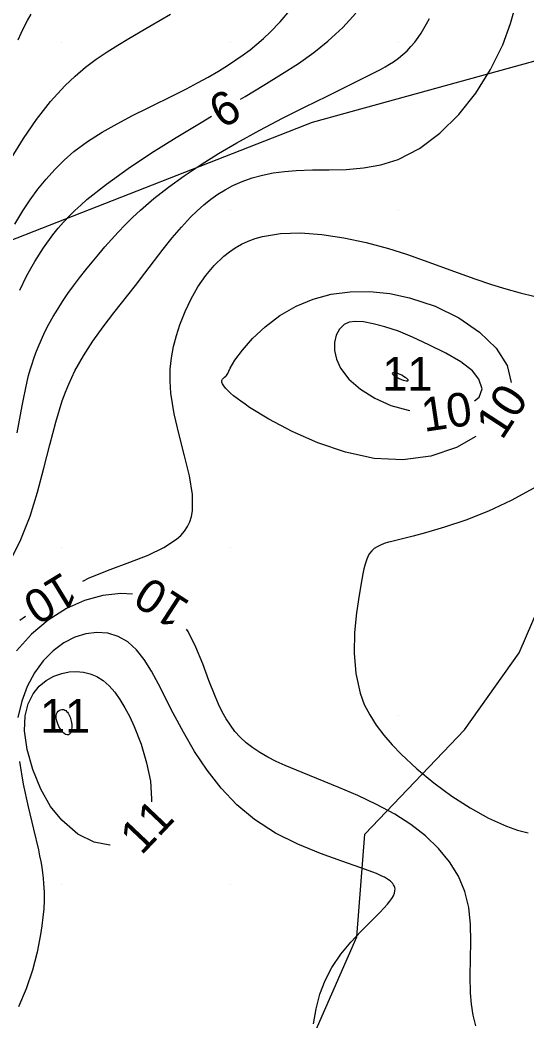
# Model space of a CAD drawing. Extents: x 2602990 to 2605851, y 618069 to 619180.
# Drawn here: x 2603217.5 to 2603247.6, y 618261.9 to 618321.3 of the extents above; entities that cross this region are included whole.
import ezdxf

# ---------------------------------------------------------------- set-up
doc = ezdxf.new("R2010")
doc.units = 0
for name, color, linetype in [('DTM Contours Major', 7, 'Continuous'), ('DTM Contours Major Text', 7, 'Continuous'), ('DTM Contours Minor', 7, 'Continuous'), ('DTM Contours Minor Text', 7, 'Continuous'), ('Exist DTM QL2 LIDAR Elevation Point', 7, 'Continuous'), ('PH Exist DTM Obscure Area', 7, 'Continuous')]:
    doc.layers.add(name, color=color, linetype=linetype)

msp = doc.modelspace()

# ---------------------------------------------------------------- linework, layer by layer
at = {"layer": 'DTM Contours Major'}
for points in [[(2603221.249, 618288.003), (2603221.638, 618288.187), (2603222.872, 618288.685), (2603224.049, 618289.127), (2603225.129, 618289.548), (2603226.068, 618289.987), (2603226.825, 618290.481), (2603227.081, 618290.715), (2603227.298, 618290.966), (2603227.475, 618291.237), (2603227.613, 618291.527), (2603227.713, 618291.839), (2603227.776, 618292.174), (2603227.775, 618293.15), (2603227.593, 618294.252), (2603227.3, 618295.44), (2603226.969, 618296.679), (2603226.67, 618297.929), (2603226.474, 618299.154), (2603226.432, 618299.878), (2603226.451, 618300.581), (2603226.524, 618301.265), (2603226.648, 618301.933), (2603226.816, 618302.587), (2603227.023, 618303.229), (2603227.327, 618304.008), (2603227.684, 618304.761), (2603228.091, 618305.477), (2603228.55, 618306.146), (2603229.06, 618306.755), (2603229.62, 618307.293), (2603229.955, 618307.558), (2603230.307, 618307.796), (2603230.677, 618308.008), (2603231.068, 618308.192), (2603231.481, 618308.347), (2603231.917, 618308.472), (2603232.999, 618308.648), (2603234.185, 618308.683), (2603235.446, 618308.595), (2603236.755, 618308.399), (2603238.087, 618308.113), (2603239.412, 618307.752), (2603240.476, 618307.415), (2603241.519, 618307.054), (2603243.548, 618306.309), (2603244.538, 618305.953), (2603245.512, 618305.626), (2603246.374, 618305.365), (2603247.219, 618305.132), (2603248.043, 618304.919)], [(2603248.03, 618293.517), (2603246.696, 618292.78), (2603245.334, 618292.152), (2603243.996, 618291.628), (2603242.737, 618291.201), (2603241.61, 618290.867), (2603240.878, 618290.672), (2603239.533, 618290.337), (2603239.409, 618290.303), (2603239.155, 618290.224), (2603238.929, 618290.138), (2603238.73, 618290.04), (2603238.556, 618289.926), (2603238.406, 618289.792), (2603238.279, 618289.633), (2603238.177, 618289.454), (2603238.092, 618289.246), (2603238.017, 618289.007), (2603237.95, 618288.735), (2603237.885, 618288.428), (2603237.818, 618288.085), (2603237.654, 618287.17), (2603237.496, 618286.104), (2603237.386, 618284.939), (2603237.36, 618283.723), (2603237.458, 618282.507), (2603237.718, 618281.342), (2603237.97, 618280.677), (2603238.291, 618280.044), (2603238.676, 618279.436), (2603239.12, 618278.848), (2603239.619, 618278.274), (2603240.166, 618277.708), (2603241.096, 618276.843), (2603242.106, 618276.009), (2603243.169, 618275.227), (2603244.259, 618274.523), (2603245.35, 618273.92), (2603246.416, 618273.441), (2603247.067, 618273.212), (2603247.695, 618273.048)], [(2603217.523, 618285.68), (2603217.847, 618285.921)]]:
    msp.add_lwpolyline(points, dxfattribs=at)
at = {"layer": 'DTM Contours Minor'}
for points in [[(2603216.947, 618289.189), (2603217.581, 618290.475), (2603218.122, 618291.862), (2603218.566, 618293.281), (2603218.947, 618294.703), (2603219.297, 618296.102), (2603219.65, 618297.448), (2603220.038, 618298.714), (2603220.221, 618299.218), (2603220.418, 618299.705), (2603220.595, 618300.1), (2603220.785, 618300.487), (2603221.291, 618301.389), (2603221.856, 618302.258), (2603222.464, 618303.102), (2603223.098, 618303.928), (2603224.383, 618305.553), (2603224.943, 618306.282), (2603226.031, 618307.709), (2603226.568, 618308.386), (2603227.108, 618309.026), (2603227.655, 618309.619), (2603228.047, 618310.002), (2603228.447, 618310.357), (2603228.857, 618310.683), (2603229.279, 618310.981), (2603229.714, 618311.25), (2603230.165, 618311.49), (2603230.726, 618311.739), (2603231.313, 618311.947), (2603231.926, 618312.116), (2603232.566, 618312.247), (2603233.234, 618312.34), (2603233.931, 618312.397), (2603234.884, 618312.425), (2603235.876, 618312.433), (2603236.893, 618312.459), (2603237.924, 618312.544), (2603238.956, 618312.727), (2603239.976, 618313.047), (2603241.248, 618313.7), (2603242.457, 618314.602), (2603243.579, 618315.711), (2603244.591, 618316.985), (2603245.467, 618318.382), (2603246.185, 618319.861), (2603246.647, 618321.116), (2603247.007, 618322.38)], [(2603216.996, 618313.095), (2603217.729, 618314.291), (2603218.506, 618315.429), (2603219.326, 618316.483), (2603220.187, 618317.43), (2603220.795, 618318.003), (2603221.418, 618318.523), (2603222.051, 618318.998), (2603222.692, 618319.435), (2603223.337, 618319.844), (2603223.981, 618320.232), (2603225.24, 618320.961), (2603226.468, 618321.671)], [(2603217.213, 618309.205), (2603217.695, 618309.993), (2603218.131, 618310.649), (2603218.589, 618311.28), (2603219.074, 618311.884), (2603219.59, 618312.458), (2603220.14, 618313.002), (2603220.731, 618313.513), (2603221.536, 618314.111), (2603222.395, 618314.661), (2603223.291, 618315.173), (2603224.209, 618315.655), (2603225.131, 618316.114), (2603226.73, 618316.903), (2603227.402, 618317.245), (2603228.057, 618317.591), (2603228.693, 618317.942), (2603229.312, 618318.301), (2603229.912, 618318.673), (2603230.347, 618318.959), (2603230.772, 618319.256), (2603231.188, 618319.566), (2603231.594, 618319.891), (2603231.992, 618320.235), (2603232.383, 618320.6), (2603232.979, 618321.218), (2603233.55, 618321.888)], [(2603217.414, 618320.163), (2603217.591, 618320.554), (2603217.777, 618320.934), (2603217.975, 618321.306), (2603218.186, 618321.671)], [(2603230.62, 618316.632), (2603230.898, 618316.796), (2603232.005, 618317.455), (2603233.061, 618318.106), (2603234.054, 618318.755), (2603234.974, 618319.41), (2603235.812, 618320.078), (2603236.265, 618320.481), (2603236.688, 618320.893), (2603237.084, 618321.313), (2603237.457, 618321.742)], [(2603217.348, 618296.799), (2603217.648, 618298.418), (2603217.744, 618298.914), (2603217.842, 618299.39), (2603217.947, 618299.849), (2603218.037, 618300.207), (2603218.134, 618300.556), (2603218.238, 618300.897), (2603218.349, 618301.232), (2603218.468, 618301.563), (2603218.597, 618301.89), (2603218.794, 618302.35), (2603219.009, 618302.806), (2603219.243, 618303.26), (2603219.495, 618303.711), (2603219.764, 618304.16), (2603220.05, 618304.608), (2603220.369, 618305.076), (2603220.704, 618305.543), (2603221.057, 618306.011), (2603221.425, 618306.481), (2603221.807, 618306.953), (2603222.204, 618307.429), (2603222.569, 618307.858), (2603222.949, 618308.29), (2603223.346, 618308.725), (2603223.766, 618309.162), (2603224.211, 618309.601), (2603224.687, 618310.042), (2603225.481, 618310.72), (2603226.349, 618311.397), (2603227.282, 618312.071), (2603228.275, 618312.738), (2603229.32, 618313.394), (2603230.409, 618314.038), (2603231.756, 618314.785), (2603233.121, 618315.501), (2603234.466, 618316.181), (2603235.757, 618316.816), (2603238.025, 618317.926), (2603238.652, 618318.244), (2603238.939, 618318.397), (2603239.21, 618318.549), (2603239.466, 618318.701), (2603239.706, 618318.856), (2603239.993, 618319.061), (2603240.26, 618319.277), (2603240.508, 618319.505), (2603240.74, 618319.75), (2603240.961, 618320.012), (2603241.171, 618320.297), (2603241.34, 618320.549), (2603241.505, 618320.819), (2603241.669, 618321.107), (2603241.832, 618321.413)], [(2603217.507, 618305.282), (2603217.932, 618306.145), (2603218.399, 618306.986), (2603218.913, 618307.798), (2603219.477, 618308.575), (2603219.787, 618308.956), (2603220.113, 618309.329), (2603220.458, 618309.695), (2603220.786, 618310.019), (2603221.133, 618310.341), (2603221.502, 618310.665), (2603222.651, 618311.582), (2603223.941, 618312.508), (2603225.334, 618313.434), (2603226.791, 618314.351), (2603228.276, 618315.25), (2603228.898, 618315.616)], [(2603229.779, 618300.221), (2603229.825, 618300.269), (2603229.86, 618300.324), (2603229.922, 618300.463), (2603230, 618300.647), (2603230.278, 618301.122), (2603230.728, 618301.727), (2603231.334, 618302.407), (2603232.079, 618303.106), (2603232.946, 618303.768), (2603233.918, 618304.338), (2603234.932, 618304.754), (2603236.01, 618305.035), (2603237.138, 618305.183), (2603238.299, 618305.198), (2603239.477, 618305.081), (2603240.658, 618304.834), (2603242.168, 618304.323), (2603243.579, 618303.629), (2603244.813, 618302.788), (2603245.794, 618301.836), (2603246.446, 618300.811), (2603246.68, 618299.802)], [(2603240, 618302.845), (2603239.178, 618303.096), (2603238.49, 618303.28), (2603237.921, 618303.392), (2603237.455, 618303.426), (2603237.075, 618303.375), (2603236.766, 618303.234), (2603236.493, 618302.97), (2603236.299, 618302.61), (2603236.196, 618302.177), (2603236.195, 618301.691), (2603236.309, 618301.175), (2603236.55, 618300.651), (2603237.054, 618299.997), (2603237.749, 618299.392), (2603238.594, 618298.864), (2603239.551, 618298.439), (2603240.578, 618298.144), (2603240.668, 618298.132)], [(2603244.516, 618298.703), (2603244.789, 618298.926), (2603244.974, 618299.428), (2603244.764, 618300), (2603244.398, 618300.499), (2603243.705, 618301.022), (2603242.802, 618301.543), (2603241.806, 618302.037), (2603240.833, 618302.48), (2603240, 618302.845)], [(2603240, 618300.314), (2603239.911, 618300.344), (2603239.833, 618300.364), (2603239.766, 618300.374), (2603239.711, 618300.375), (2603239.67, 618300.369), (2603239.643, 618300.357), (2603239.632, 618300.336), (2603239.637, 618300.31), (2603239.659, 618300.28), (2603239.694, 618300.245), (2603239.798, 618300.168), (2603239.884, 618300.117), (2603240.081, 618300.018), (2603240.281, 618299.939), (2603240.373, 618299.911), (2603240.448, 618299.894), (2603240.51, 618299.887), (2603240.552, 618299.894), (2603240.571, 618299.914), (2603240.564, 618299.949), (2603240.526, 618300), (2603240.473, 618300.046), (2603240.395, 618300.102), (2603240.301, 618300.163), (2603240.199, 618300.223), (2603240.096, 618300.275), (2603240, 618300.314)], [(2603244.587, 618296.588), (2603243.45, 618295.942), (2603241.921, 618295.424), (2603240.258, 618295.196), (2603238.558, 618295.29), (2603236.857, 618295.651), (2603235.211, 618296.206), (2603233.676, 618296.883), (2603232.307, 618297.612), (2603231.16, 618298.32), (2603230.889, 618298.503), (2603230.64, 618298.679), (2603230.413, 618298.847), (2603230.211, 618299.007), (2603230.032, 618299.159), (2603229.878, 618299.302), (2603229.736, 618299.453), (2603229.627, 618299.591), (2603229.554, 618299.716), (2603229.516, 618299.826), (2603229.517, 618299.921), (2603229.556, 618300), (2603229.584, 618300.04), (2603229.662, 618300.112), (2603229.745, 618300.182), (2603229.779, 618300.221)], [(2603224.201, 618287.219), (2603223.508, 618287.265), (2603222.437, 618287.146), (2603221.351, 618286.845), (2603220.283, 618286.371), (2603219.201, 618285.685), (2603218.206, 618284.837), (2603217.324, 618283.857)], [(2603234.955, 618261.697), (2603235.101, 618262.592), (2603235.33, 618263.453), (2603235.643, 618264.272), (2603236.04, 618265.043), (2603236.569, 618265.828), (2603237.162, 618266.549), (2603237.778, 618267.206), (2603238.913, 618268.334), (2603239.35, 618268.806), (2603239.49, 618268.981), (2603239.605, 618269.146), (2603239.694, 618269.302), (2603239.756, 618269.45), (2603239.789, 618269.591), (2603239.792, 618269.724), (2603239.778, 618269.806), (2603239.75, 618269.886), (2603239.709, 618269.963), (2603239.655, 618270.039), (2603239.587, 618270.112), (2603239.506, 618270.184), (2603239.405, 618270.259), (2603239.29, 618270.333), (2603239.16, 618270.406), (2603239.016, 618270.479), (2603238.857, 618270.553), (2603238.684, 618270.626), (2603237.758, 618270.971), (2603236.628, 618271.359), (2603235.363, 618271.815), (2603234.031, 618272.363), (2603232.702, 618273.028), (2603231.446, 618273.835), (2603230.405, 618274.712), (2603229.473, 618275.698), (2603228.639, 618276.765), (2603227.893, 618277.881), (2603227.226, 618279.017), (2603226.626, 618280.143), (2603225.757, 618281.868), (2603225.337, 618282.642), (2603224.903, 618283.332), (2603224.44, 618283.919), (2603223.929, 618284.383), (2603223.359, 618284.709), (2603222.742, 618284.896), (2603222.094, 618284.949), (2603221.431, 618284.871), (2603220.771, 618284.667), (2603220.129, 618284.339), (2603219.485, 618283.861), (2603218.897, 618283.26), (2603218.382, 618282.55), (2603217.957, 618281.745), (2603217.638, 618280.857), (2603217.395, 618279.904)], [(2603244.587, 618261.584), (2603244.441, 618262.212), (2603244.339, 618262.866), (2603244.279, 618263.543), (2603244.258, 618264.535), (2603244.298, 618266.582), (2603244.277, 618267.605), (2603244.173, 618268.605), (2603243.946, 618269.566), (2603243.565, 618270.475), (2603243.035, 618271.327), (2603242.375, 618272.121), (2603241.601, 618272.857), (2603240.728, 618273.532), (2603239.775, 618274.147), (2603238.701, 618274.731), (2603237.585, 618275.258), (2603236.455, 618275.74), (2603234.269, 618276.621), (2603233.271, 618277.043), (2603232.738, 618277.29), (2603232.239, 618277.544), (2603231.775, 618277.809), (2603231.345, 618278.093), (2603230.95, 618278.399), (2603230.59, 618278.733), (2603230.29, 618279.068), (2603230.016, 618279.431), (2603229.765, 618279.822), (2603229.532, 618280.239), (2603229.315, 618280.684), (2603229.11, 618281.154), (2603228.742, 618282.102), (2603228.373, 618283.091), (2603227.973, 618284.073), (2603227.511, 618284.998), (2603227.416, 618285.138)], [(2603217.823, 618280), (2603218.012, 618280.716), (2603218.298, 618281.295), (2603218.66, 618281.749), (2603219.078, 618282.094), (2603219.531, 618282.342), (2603220, 618282.509), (2603220.438, 618282.601), (2603220.868, 618282.63), (2603221.288, 618282.596), (2603221.696, 618282.496), (2603222.088, 618282.327), (2603222.461, 618282.089), (2603222.814, 618281.78), (2603223.147, 618281.405), (2603223.461, 618280.969), (2603223.758, 618280.478), (2603224.039, 618279.937), (2603224.306, 618279.351), (2603224.71, 618278.305), (2603225.042, 618277.206), (2603225.264, 618276.105), (2603225.342, 618275.054), (2603225.324, 618274.888)], [(2603219.68, 618280), (2603219.701, 618280.108), (2603219.741, 618280.196), (2603219.795, 618280.266), (2603219.859, 618280.317), (2603219.929, 618280.351), (2603220, 618280.369), (2603220.064, 618280.371), (2603220.126, 618280.361), (2603220.185, 618280.338), (2603220.24, 618280.304), (2603220.292, 618280.26), (2603220.341, 618280.207), (2603220.386, 618280.146), (2603220.427, 618280.077), (2603220.464, 618280.002), (2603220.497, 618279.922), (2603220.526, 618279.838), (2603220.55, 618279.75), (2603220.581, 618279.602), (2603220.598, 618279.454), (2603220.603, 618279.311), (2603220.592, 618279.179), (2603220.567, 618279.063), (2603220.526, 618278.967), (2603220.473, 618278.902), (2603220.405, 618278.865), (2603220.323, 618278.86), (2603220.228, 618278.892), (2603220.12, 618278.966), (2603220, 618279.086), (2603219.92, 618279.206), (2603219.837, 618279.358), (2603219.763, 618279.528), (2603219.706, 618279.701), (2603219.675, 618279.863), (2603219.68, 618280)], [(2603222.886, 618272.316), (2603222.859, 618272.312), (2603221.935, 618272.489), (2603220.967, 618272.971), (2603220, 618273.79), (2603219.345, 618274.599), (2603218.765, 618275.641), (2603218.292, 618276.809), (2603217.956, 618277.995), (2603217.789, 618279.095), (2603217.823, 618280)], [(2603217.489, 618277.287), (2603217.717, 618275.929), (2603218.015, 618274.579), (2603218.333, 618273.27), (2603218.619, 618272.033), (2603218.692, 618271.681), (2603218.757, 618271.337), (2603218.813, 618271), (2603218.861, 618270.67), (2603218.9, 618270.346), (2603218.928, 618270.026), (2603218.953, 618269.525), (2603218.954, 618269.028), (2603218.932, 618268.533), (2603218.889, 618268.034), (2603218.827, 618267.527), (2603218.747, 618267.009), (2603218.542, 618265.962), (2603218.263, 618264.88), (2603217.898, 618263.786), (2603217.436, 618262.703)]]:
    msp.add_lwpolyline(points, dxfattribs=at)
at = {"layer": 'Exist DTM QL2 LIDAR Elevation Point'}
for p, q in [((2603220, 618320), (2603220, 618320)), ((2603230, 618320), (2603230, 618320)), ((2603240, 618320), (2603240, 618320)), ((2603220, 618310), (2603220, 618310)), ((2603230, 618310), (2603230, 618310)), ((2603240, 618310), (2603240, 618310)), ((2603220, 618300), (2603220, 618300)), ((2603230, 618300), (2603230, 618300)), ((2603240, 618300), (2603240, 618300)), ((2603220, 618290), (2603220, 618290)), ((2603230, 618290), (2603230, 618290)), ((2603240, 618290), (2603240, 618290)), ((2603220, 618280), (2603220, 618280)), ((2603230, 618280), (2603230, 618280)), ((2603240, 618280), (2603240, 618280)), ((2603220, 618270), (2603220, 618270)), ((2603230, 618270), (2603230, 618270)), ((2603240, 618270), (2603240, 618270))]:
    msp.add_line(p, q, dxfattribs=at)
at = {"layer": 'PH Exist DTM Obscure Area'}
for points in [[(2603301.286, 618333.579), (2603234.869, 618315.243), (2603198.873, 618301.136), (2603152.972, 618286.732), (2603122.123, 618276.477)], [(2603214.095, 618205.908), (2603236.88, 618213.413), (2603242.897, 618213.478), (2603249.693, 618219.367), (2603251.965, 618230.407), (2603242.886, 618234.25), (2603237.813, 618233.008), (2603228.59, 618230.749), (2603221.465, 618233.662), (2603224.846, 618242.398), (2603230.879, 618251.696), (2603237.516, 618266.865), (2603238.005, 618272.966), (2603243.908, 618279.156), (2603247.154, 618283.746), (2603250.298, 618290.986), (2603258.623, 618297.971), (2603270.971, 618303.439), (2603273.862, 618305.958), (2603281.14, 618310.76)]]:
    msp.add_lwpolyline(points, dxfattribs=at)

# ---------------------------------------------------------------- texts
at = {"layer": 'DTM Contours Major Text'}
msp.add_text('10', height=2, rotation=211.46253, dxfattribs=at).set_placement((2603220.075, 618288.59))
at = {"layer": 'DTM Contours Minor Text'}
for s, rotation, p in [('9', 210.53229, (2603229.814, 618317.318)), ('10', 8.44444, (2603241.52, 618296.86)), ('10', 56.92501, (2603246.148, 618296.323)), ('10', 147.08086, (2603227.708, 618286.725)), ('11', 46.5438, (2603224.737, 618271.667))]:
    msp.add_text(s, height=2, rotation=rotation, dxfattribs=at).set_placement(p)
for p in [(2603239.039, 618299.314), (2603218.719, 618279)]:
    msp.add_text('11', height=2, dxfattribs=at).set_placement(p)

doc.saveas('drawing.dxf')
